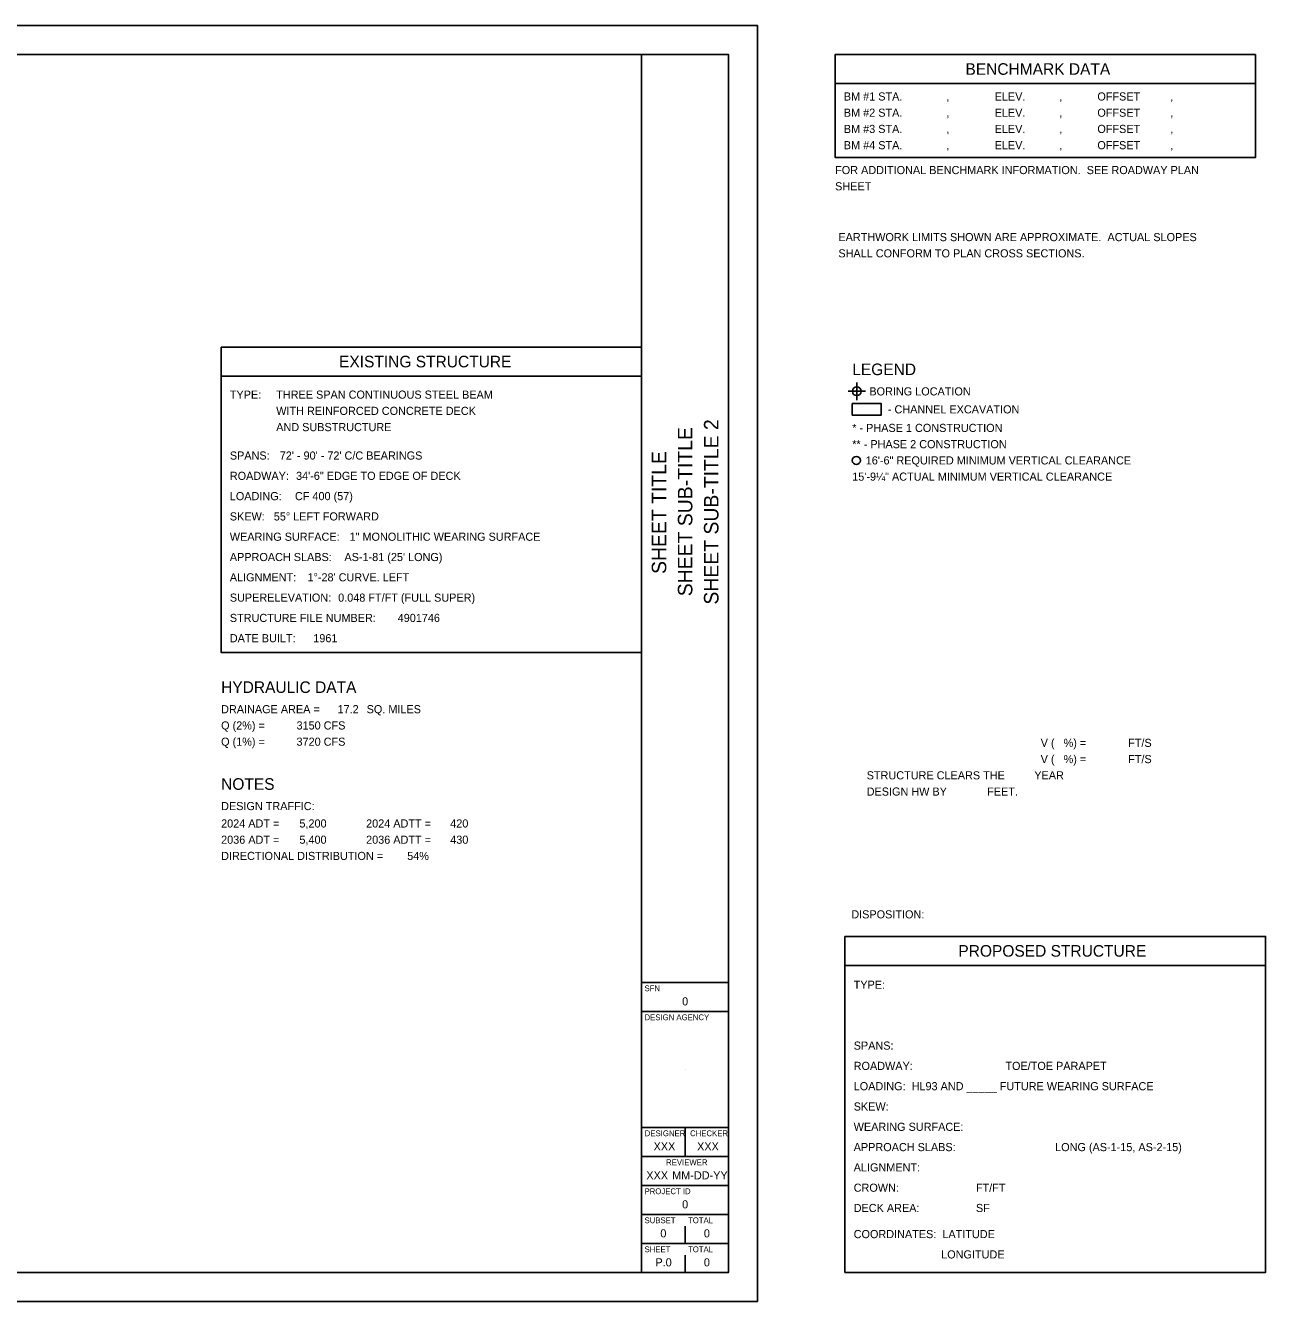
# Model space of a CAD drawing. Extents: x -30.3 to 42.8, y 0 to 22.
# Drawn here: x 21.38 to 42.76, y 0 to 22 of the extents above; entities that cross this region are included whole.
import ezdxf

# ---------------------------------------------------------------- set-up
doc = ezdxf.new("R2010")
doc.units = 0
for name, color, linetype in [('_CIVIL_CONSTRUCTION', 7, 'Continuous'), ('MT_P_CL_Double_Solid', 7, 'Continuous'), ('MT_P_Edge_Line', 7, 'Continuous'), ('MT_P_PCB', 7, 'Continuous')]:
    doc.layers.add(name, color=color, linetype=linetype)

msp = doc.modelspace()

# ---------------------------------------------------------------- linework, layer by layer
at = {"layer": '_CIVIL_CONSTRUCTION'}
for p, q in [((35.708, 15.693), (35.708, 15.843)), ((35.708, 15.693), (35.558, 15.693)), ((35.708, 15.693), (35.633, 15.693)), ((35.708, 15.768), (35.708, 15.693)), ((35.708, 15.693), (35.708, 15.543)), ((35.708, 15.693), (35.858, 15.693)), ((35.708, 15.618), (35.708, 15.693)), ((35.708, 15.693), (35.783, 15.693))]:
    msp.add_line(p, q, dxfattribs=at)
msp.add_circle((35.708, 15.693), 0.075, dxfattribs=at)
for start, end in [(90, 180), (270, 360)]:
    msp.add_arc((35.708, 15.693), 0.075, start, end, dxfattribs=at)
at = {"layer": 'MT_P_CL_Double_Solid'}
for p, q in [((35.336, 21), (42.586, 21)), ((32, 15.956), (24.75, 15.956)), ((42.756, 5.795), (35.506, 5.795)), ((32.75, 4), (32.75, 4)), ((32.75, 1), (32.75, 1.3)), ((32.375, 0.675), (32.375, 0.675)), ((32.75, 0.5), (32.75, 0.8))]:
    msp.add_line(p, q, dxfattribs=at)
for points in [[(42.586, 21.5), (35.336, 21.5), (35.336, 19.727), (42.586, 19.727)], [(24.75, 16.456), (32, 16.456), (32, 11.192), (24.75, 11.192)], [(35.631, 15.482), (36.131, 15.482), (36.131, 15.282), (35.631, 15.282)], [(35.506, 6.295), (42.756, 6.295), (42.756, 0.5), (35.506, 0.5)]]:
    msp.add_lwpolyline(points, close=True, dxfattribs=at)
msp.add_circle((35.701, 14.501), 0.07, dxfattribs=at)
at = {"layer": 'MT_P_Edge_Line'}
for p, q in [((32, 0.5), (32, 21.5)), ((32, 5.5), (33.5, 5.5)), ((32, 5), (33.5, 5)), ((32, 3), (33.5, 3)), ((32.75, 3), (32.75, 2.5)), ((32, 2.5), (33.5, 2.5)), ((32, 2), (33.5, 2)), ((32, 1.5), (33.5, 1.5)), ((32, 1), (33.5, 1))]:
    msp.add_line(p, q, dxfattribs=at)
msp.add_lwpolyline([(1.5, 21.5), (33.5, 21.5), (33.5, 0.5), (1.5, 0.5)], close=True, dxfattribs=at)
at = {"layer": 'MT_P_PCB'}
msp.add_lwpolyline([(0, 0), (34, 0), (34, 22), (0, 22)], close=True, dxfattribs=at)

# ---------------------------------------------------------------- texts
at = {"layer": 'MT_P_CL_Double_Solid'}
for s, height, p in [('BENCHMARK DATA', 0.2, (37.583, 21.15)), ('BM #1 STA.', 0.14, (35.486, 20.707)), ('         ,', 0.14, (36.786, 20.707)), ('ELEV.', 0.14, (38.086, 20.707)), ('       ,', 0.14, (38.836, 20.707)), ('OFFSET', 0.14, (39.857, 20.707)), ('      ,', 0.14, (40.801, 20.707)), ('BM #2 STA.', 0.14, (35.486, 20.427)), ('ELEV.', 0.14, (38.086, 20.427)), ('OFFSET', 0.14, (39.857, 20.427)), ('BM #3 STA.', 0.14, (35.486, 20.147)), ('         ,', 0.14, (36.786, 20.427)), ('ELEV.', 0.14, (38.086, 20.147)), ('       ,', 0.14, (38.836, 20.427)), ('OFFSET', 0.14, (39.857, 20.147)), ('      ,', 0.14, (40.801, 20.427)), ('         ,', 0.14, (36.786, 20.147)), ('       ,', 0.14, (38.836, 20.147)), ('      ,', 0.14, (40.801, 20.147)), ('BM #4 STA.', 0.14, (35.486, 19.867)), ('         ,', 0.14, (36.786, 19.867)), ('ELEV.', 0.14, (38.086, 19.867)), ('       ,', 0.14, (38.836, 19.867)), ('OFFSET', 0.14, (39.857, 19.867)), ('      ,', 0.14, (40.801, 19.867)), ('FOR ADDITIONAL BENCHMARK INFORMATION.  SEE ROADWAY PLAN', 0.14, (35.336, 19.438)), ('SHEET      ', 0.14, (35.336, 19.158)), ('EARTHWORK LIMITS SHOWN ARE APPROXIMATE.  ACTUAL SLOPES', 0.14, (35.392, 18.282)), ('SHALL CONFORM TO PLAN CROSS SECTIONS.', 0.14, (35.392, 18.002)), ('EXISTING STRUCTURE', 0.2, (26.783, 16.106)), ('LEGEND', 0.2, (35.631, 15.972)), ('TYPE:', 0.14, (24.9, 15.566)), ('THREE SPAN CONTINUOUS STEEL BEAM', 0.14, (25.7, 15.566)), ('BORING LOCATION', 0.14, (35.926, 15.622)), ('WITH REINFORCED CONCRETE DECK', 0.14, (25.7, 15.286)), ('- CHANNEL EXCAVATION', 0.14, (36.245, 15.312)), ('AND SUBSTRUCTURE', 0.14, (25.7, 15.006)), ('* - PHASE 1 CONSTRUCTION', 0.14, (35.631, 14.992)), ('** - PHASE 2 CONSTRUCTION', 0.14, (35.631, 14.712)), ('SPANS:', 0.14, (24.9, 14.516)), ("72' - 90' - 72' C/C BEARINGS", 0.14, (25.761, 14.516)), ('ROADWAY:', 0.14, (24.9, 14.166)), ('34\'-6" EDGE TO EDGE OF DECK', 0.14, (26.042, 14.166)), ('LOADING:', 0.14, (24.9, 13.816)), ('CF 400 (57)', 0.14, (26.023, 13.816)), ('SKEW:', 0.14, (24.9, 13.466)), ('55° LEFT FORWARD', 0.14, (25.658, 13.466)), ('WEARING SURFACE:', 0.14, (24.9, 13.116)), ('1" MONOLITHIC WEARING SURFACE', 0.14, (26.965, 13.116)), ('APPROACH SLABS:', 0.14, (24.9, 12.766)), ("AS-1-81 (25' LONG)", 0.14, (26.876, 12.766)), ('ALIGNMENT:', 0.14, (24.9, 12.416)), ("1°-28' CURVE. LEFT", 0.14, (26.239, 12.416)), ('SUPERELEVATION:', 0.14, (24.9, 12.066)), ('0.048 FT/FT (FULL SUPER)', 0.14, (26.768, 12.066)), ('STRUCTURE FILE NUMBER:', 0.14, (24.9, 11.716)), ('4901746', 0.14, (27.794, 11.716)), ('DATE BUILT:', 0.14, (24.9, 11.366)), ('1961', 0.14, (26.339, 11.366)), ('HYDRAULIC DATA', 0.2, (24.75, 10.492)), ('DRAINAGE AREA =', 0.14, (24.75, 10.142)), ('17.2', 0.14, (26.757, 10.142)), ('SQ. MILES', 0.14, (27.259, 10.142)), ('Q (2%) =', 0.14, (24.75, 9.862)), ('3150 CFS', 0.14, (26.05, 9.862)), ('Q (1%) =', 0.14, (24.75, 9.582)), ('3720 CFS', 0.14, (26.05, 9.582)), ('V (   %) =', 0.14, (38.88, 9.562)), ('    FT/S', 0.14, (40.18, 9.562)), ('V (   %) =', 0.14, (38.88, 9.282)), ('    FT/S', 0.14, (40.18, 9.282)), ('NOTES', 0.2, (24.75, 8.822)), ('STRUCTURE CLEARS THE', 0.14, (35.88, 9.002)), ('YEAR', 0.14, (38.77, 9.002)), ('DESIGN HW BY', 0.14, (35.88, 8.722)), ('FEET.', 0.14, (37.957, 8.722)), ('DESIGN TRAFFIC:', 0.14, (24.75, 8.472)), ('2024 ADT =', 0.14, (24.75, 8.172)), ('5,200', 0.14, (26.1, 8.172)), ('2024 ADTT =', 0.14, (27.25, 8.172)), ('420', 0.14, (28.7, 8.172)), ('2036 ADT =', 0.14, (24.75, 7.892)), ('5,400', 0.14, (26.1, 7.892)), ('2036 ADTT =', 0.14, (27.25, 7.892)), ('430', 0.14, (28.7, 7.892)), ('DIRECTIONAL DISTRIBUTION =', 0.14, (24.75, 7.612)), ('54%', 0.14, (27.958, 7.612)), ('DISPOSITION:', 0.14, (35.615, 6.605)), ('PROPOSED STRUCTURE', 0.2, (37.461, 5.945)), ('TYPE:', 0.14, (35.656, 5.392)), ('SFN', 0.1, (32.05, 5.35)), ('0', 0.14, (32.698, 5.105)), ('DESIGN AGENCY', 0.1, (32.05, 4.85)), ('SPANS:', 0.14, (35.656, 4.342)), ('ROADWAY:', 0.14, (35.656, 3.992)), ('TOE/TOE PARAPET', 0.14, (38.271, 3.992)), ('LOADING:  HL93 AND _____ FUTURE WEARING SURFACE', 0.14, (35.656, 3.642)), ('SKEW:', 0.14, (35.656, 3.292)), ('WEARING SURFACE:', 0.14, (35.656, 2.942)), ('DESIGNER', 0.1, (32.054, 2.85)), ('CHECKER', 0.1, (32.835, 2.85)), ('XXX', 0.14, (32.206, 2.605)), ('XXX', 0.14, (32.956, 2.605)), ('APPROACH SLABS:', 0.14, (35.656, 2.592)), ('LONG (AS-1-15, AS-2-15)', 0.14, (39.129, 2.592)), ('REVIEWER', 0.1, (32.422, 2.35)), ('XXX', 0.14, (32.081, 2.105)), ('MM-DD-YY', 0.14, (32.527, 2.105)), ('ALIGNMENT:', 0.14, (35.656, 2.242)), ('CROWN:', 0.14, (35.656, 1.892)), ('FT/FT', 0.14, (37.764, 1.892)), ('PROJECT ID', 0.1, (32.05, 1.85)), ('0', 0.14, (32.698, 1.605)), ('DECK AREA:', 0.14, (35.656, 1.542)), ('SF', 0.14, (37.764, 1.542)), ('SUBSET', 0.1, (32.05, 1.35)), ('TOTAL', 0.1, (32.8, 1.35)), ('0', 0.14, (32.323, 1.105)), ('0', 0.14, (33.073, 1.105)), ('COORDINATES:  LATITUDE', 0.14, (35.656, 1.092)), ('SHEET', 0.1, (32.05, 0.85)), ('TOTAL', 0.1, (32.8, 0.85)), ('                             LONGITUDE', 0.14, (35.656, 0.742)), ('P.0', 0.14, (32.238, 0.605)), ('0', 0.14, (33.073, 0.605))]:
    msp.add_text(s, height=height, dxfattribs=at).set_placement(p)
for s, height, rotation, p in [('SHEET SUB-TITLE 2', 0.25, 90, (33.325, 12.016)), ('SHEET SUB-TITLE', 0.25, 90, (32.875, 12.16)), ('SHEET TITLE', 0.25, 90, (32.425, 12.544)), ('16\'-6" REQUIRED MINIMUM VERTICAL CLEARANCE', 0.14, 0, (35.864, 14.432)), ('15\'-9¼" ACTUAL MINIMUM VERTICAL CLEARANCE', 0.14, 0, (35.631, 14.152))]:
    msp.add_text(s, height=height, rotation=rotation, dxfattribs=at).set_placement(p)

doc.saveas('drawing.dxf')
